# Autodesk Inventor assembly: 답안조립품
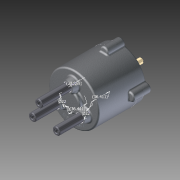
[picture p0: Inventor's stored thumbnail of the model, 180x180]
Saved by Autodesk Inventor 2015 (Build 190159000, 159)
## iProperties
Created: 2014-12
Part Number: 답안조립품
Document SubType Name: Assembly
Designer: Deny
Mass: 2156.68 g
Surface Area: 1801.24 cm^2
Volume: 438.525 cm^3
Density: 4.91804 g/cm^3
Author: Deny
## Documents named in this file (14)
- C:\Users\Deny\Desktop\Inventor1급-배찬우\답안조립품.iam
- C:\Users\Deny\Desktop\Inventor1급-배찬우\몸체.ipt
- C:\Users\Deny\Desktop\Inventor1급-배찬우\판캠.ipt
- C:\Users\Deny\Desktop\Inventor1급-배찬우\베어링 NA 4900.ipt
- C:\Users\Deny\Desktop\Inventor1급-배찬우\메인 축.ipt
- C:\Users\Deny\Desktop\Inventor1급-배찬우\멈춤링 10 x 1.ipt
- C:\Users\Deny\Desktop\Inventor1급-배찬우\멈춤링 22 x 1.2.ipt
- C:\Users\Deny\Desktop\Inventor1급-배찬우\슬라이드 축.ipt
- C:\Users\Deny\Desktop\Inventor1급-배찬우\커버.ipt
- C:\Users\Deny\Desktop\Inventor1급-배찬우\오일실.ipt
- C:\Users\Deny\Desktop\Inventor1급-배찬우\M5x0.5x20.ipt
- C:\Users\Deny\Desktop\Inventor1급-배찬우\가변스프링01.ipt
- C:\Users\Deny\Desktop\Inventor1급-배찬우\가변스프링02.ipt
- C:\Users\Deny\Desktop\Inventor1급-배찬우\가변스프링03.ipt
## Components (7 placed, 4 different names)
1. 가변스프링01:1 — Mate:32, Mate:35, Mate:38
2. 가변스프링02:1 — Mate:33, Mate:36, Mate:39
3. 가변스프링03:1 — Mate:34, Mate:37, Mate:40
4. M5x0.5x20:1 — Insert:4
5. M5x0.5x20:2
6. M5x0.5x20:3
7. M5x0.5x20:4
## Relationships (10: Mate 9, Insert 1)
- Insert:4: M5x0.5x20:1
- Mate:32: 가변스프링01:1
- Mate:33: 가변스프링02:1
- Mate:34: 가변스프링03:1
- Mate:35: 가변스프링01:1
- Mate:36: 가변스프링02:1
- Mate:37: 가변스프링03:1
- Mate:38: 가변스프링01:1
- Mate:39: 가변스프링02:1
- Mate:40: 가변스프링03:1
